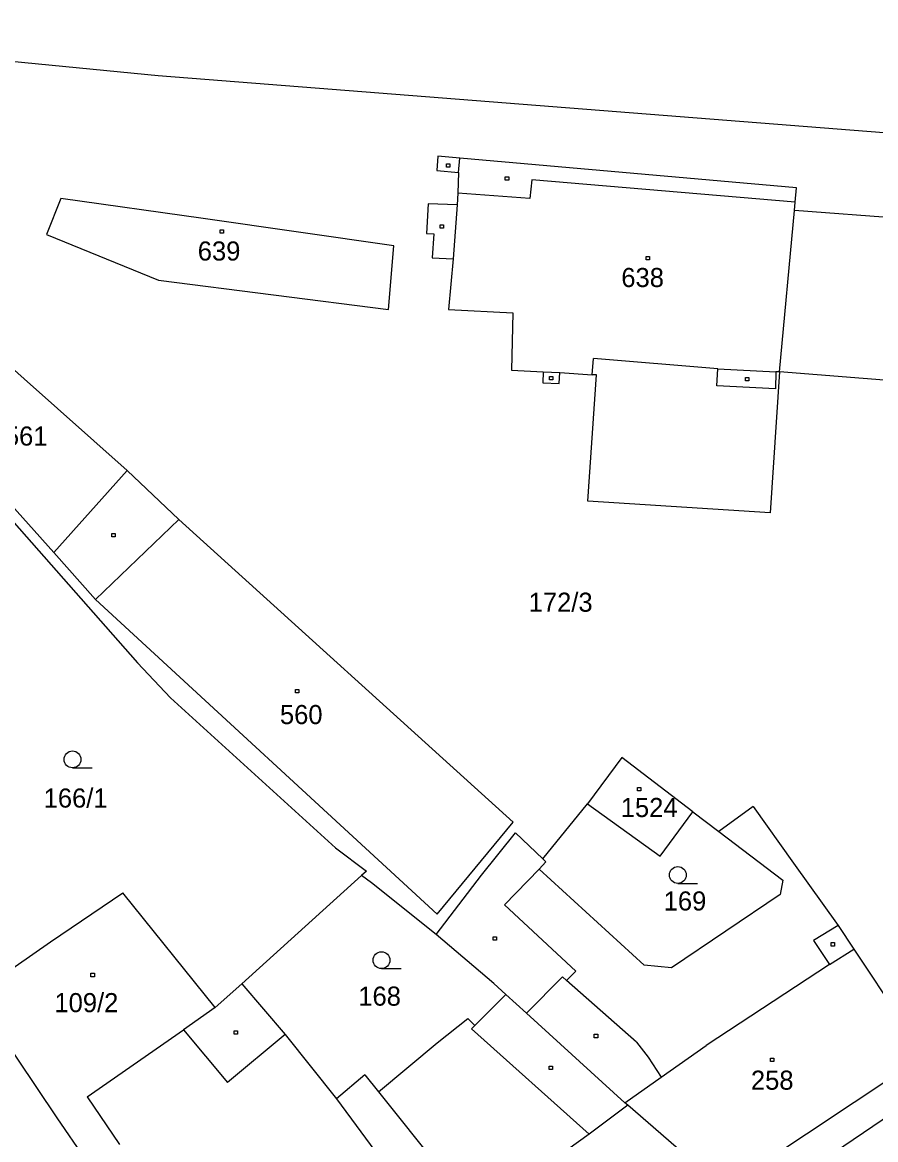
# Model space of a CAD drawing. Extents: x -711879 to -711361, y -1048782 to -1048177.
# Drawn here: x -711745.8 to -711669.9, y -1048542.7 to -1048443.3 of the extents above; entities that cross this region are included whole.
import ezdxf

# ---------------------------------------------------------------- set-up
doc = ezdxf.new("R2010")
doc.units = 0
for name, color, linetype in [('Vrstva 1', 7, 'Continuous'), ('Vrstva 14', 7, 'Continuous'), ('Vrstva 15', 7, 'Continuous'), ('Vrstva 2', 7, 'Continuous'), ('Vrstva 23', 7, 'Continuous'), ('Vrstva 25', 7, 'Continuous'), ('Vrstva 46', 7, 'Continuous')]:
    doc.layers.add(name, color=color, linetype=linetype)

msp = doc.modelspace()

# ---------------------------------------------------------------- linework, layer by layer
at = {"layer": 'Vrstva 1'}
for p, q in [((-711782.37, -1048443.28), (-711733.69, -1048448.01)), ((-711733.69, -1048448.01), (-711654.61, -1048454.24)), ((-711708.81, -1048455.2), (-711708.89, -1048456.47)), ((-711706.85, -1048455.37), (-711708.81, -1048455.2)), ((-711676.89, -1048458), (-711706.85, -1048455.37)), ((-711708.89, -1048456.47), (-711706.96, -1048456.63)), ((-711706.96, -1048456.63), (-711707.02, -1048458.48)), ((-711707.02, -1048458.48), (-711707.08, -1048459.53)), ((-711677.03, -1048459.27), (-711676.89, -1048458)), ((-711742.35, -1048458.96), (-711743.64, -1048462.17)), ((-711729.69, -1048460.74), (-711742.35, -1048458.96)), ((-711709.66, -1048459.43), (-711709.82, -1048462.08)), ((-711707.08, -1048459.53), (-711709.66, -1048459.43)), ((-711677.08, -1048460.02), (-711677.03, -1048459.27)), ((-711678.42, -1048474.4), (-711677.08, -1048460.02)), ((-711660, -1048461.34), (-711677.08, -1048460.02)), ((-711712.73, -1048463.18), (-711729.69, -1048460.74)), ((-711743.64, -1048462.17), (-711733.67, -1048466.24)), ((-711709.82, -1048462.08), (-711709.17, -1048462.11)), ((-711709.17, -1048462.11), (-711709.33, -1048464.24)), ((-711713.2, -1048468.83), (-711712.73, -1048463.18)), ((-711709.33, -1048464.24), (-711707.46, -1048464.32)), ((-711707.46, -1048464.32), (-711707.87, -1048468.83)), ((-711733.67, -1048466.24), (-711713.2, -1048468.83)), ((-711707.87, -1048468.83), (-711702.15, -1048469.14)), ((-711702.15, -1048469.14), (-711702.26, -1048474.24)), ((-711747.61, -1048473.24), (-711745.62, -1048475.02)), ((-711702.26, -1048474.24), (-711699.43, -1048474.38)), ((-711699.43, -1048474.38), (-711699.47, -1048475.36)), ((-711698.02, -1048475.42), (-711697.97, -1048474.45)), ((-711697.97, -1048474.45), (-711695.09, -1048474.64)), ((-711678.42, -1048474.4), (-711679.25, -1048486.93)), ((-711648.15, -1048476.76), (-711678.42, -1048474.4)), ((-711745.62, -1048475.02), (-711736.45, -1048483.16)), ((-711699.47, -1048475.36), (-711698.02, -1048475.42)), ((-711695.47, -1048485.89), (-711694.7, -1048474.65)), ((-711694.7, -1048474.65), (-711695.09, -1048474.64)), ((-711742.97, -1048490.46), (-711753.19, -1048479.09)), ((-711736.45, -1048483.16), (-711731.85, -1048487.53)), ((-711679.25, -1048486.93), (-711695.47, -1048485.89)), ((-711747.16, -1048487.08), (-711735.52, -1048500.3)), ((-711731.85, -1048487.53), (-711739.27, -1048494.66)), ((-711702.1, -1048514.46), (-711731.85, -1048487.53)), ((-711739.27, -1048494.66), (-711742.97, -1048490.46)), ((-711739.27, -1048494.66), (-711708.88, -1048522.66)), ((-711735.52, -1048500.3), (-711732.59, -1048503.39)), ((-711732.59, -1048503.39), (-711717.93, -1048516.75)), ((-711692.45, -1048508.71), (-711695.49, -1048512.83)), ((-711686.12, -1048513.55), (-711692.45, -1048508.71)), ((-711699.48, -1048517.72), (-711695.49, -1048512.83)), ((-711695.49, -1048512.83), (-711689.04, -1048517.5)), ((-711680.76, -1048513.07), (-711683.81, -1048515.31)), ((-711680.76, -1048513.07), (-711677.16, -1048518.12)), ((-711689.04, -1048517.5), (-711686.12, -1048513.55)), ((-711686.12, -1048513.55), (-711683.81, -1048515.31)), ((-711708.88, -1048522.66), (-711702.1, -1048514.46)), ((-711704.92, -1048519.17), (-711701.89, -1048515.43)), ((-711701.89, -1048515.43), (-711699.48, -1048517.72)), ((-711683.81, -1048515.31), (-711678.11, -1048519.64)), ((-711717.93, -1048516.75), (-711715.17, -1048518.83)), ((-711699.8, -1048518.66), (-711699.2, -1048518)), ((-711699.2, -1048518), (-711699.48, -1048517.72)), ((-711677.16, -1048518.12), (-711673.19, -1048523.66)), ((-711715.59, -1048519.2), (-711726.24, -1048528.87)), ((-711715.17, -1048518.83), (-711715.59, -1048519.2)), ((-711714.72, -1048519.88), (-711715.59, -1048519.2)), ((-711708.95, -1048524.46), (-711704.92, -1048519.17)), ((-711690.45, -1048527.19), (-711699.8, -1048518.66)), ((-711708.95, -1048524.46), (-711714.72, -1048519.88)), ((-711678.11, -1048519.64), (-711678.37, -1048520.9)), ((-711743.26, -1048525.11), (-711736.84, -1048520.76)), ((-711728.61, -1048530.95), (-711736.84, -1048520.76)), ((-711678.37, -1048520.9), (-711688.03, -1048527.44)), ((-711673.19, -1048523.66), (-711671.8, -1048525.77)), ((-711750.06, -1048529.83), (-711743.26, -1048525.11)), ((-711703.83, -1048528.84), (-711708.95, -1048524.46)), ((-711671.8, -1048525.77), (-711665.54, -1048535.25)), ((-711688.03, -1048527.44), (-711690.45, -1048527.19)), ((-711728.61, -1048530.95), (-711726.24, -1048528.87)), ((-711726.24, -1048528.87), (-711722.39, -1048533.38)), ((-711702.77, -1048529.8), (-711703.83, -1048528.84)), ((-711705.52, -1048532.56), (-711702.77, -1048529.8)), ((-711700.91, -1048531.48), (-711702.77, -1048529.8)), ((-711728.61, -1048530.95), (-711731.45, -1048532.94)), ((-711742.68, -1048540.77), (-711748.68, -1048531.86)), ((-711708.87, -1048534.1), (-711706.14, -1048531.93)), ((-711706.14, -1048531.93), (-711705.52, -1048532.56)), ((-711692.18, -1048539.46), (-711700.91, -1048531.48)), ((-711740.02, -1048538.92), (-711731.45, -1048532.94)), ((-711722.39, -1048533.38), (-711717.84, -1048539.08)), ((-711714.1, -1048538.46), (-711708.87, -1048534.1)), ((-711683.36, -1048547.06), (-711665.54, -1048535.25)), ((-711715.3, -1048536.96), (-711717.84, -1048539.08)), ((-711715.3, -1048536.96), (-711714.1, -1048538.46)), ((-711740.02, -1048538.92), (-711737.13, -1048543.16)), ((-711717.84, -1048539.08), (-711710.59, -1048548.86)), ((-711691.92, -1048539.67), (-711692.18, -1048539.46)), ((-711683.36, -1048547.06), (-711691.92, -1048539.67)), ((-711740.17, -1048544.47), (-711742.68, -1048540.77))]:
    msp.add_line(p, q, dxfattribs=at)
at = {"layer": 'Vrstva 2'}
for p, q in [((-711706.96, -1048456.63), (-711706.85, -1048455.37)), ((-711700.46, -1048457.3), (-711700.63, -1048458.96)), ((-711677.03, -1048459.27), (-711700.46, -1048457.3)), ((-711700.63, -1048458.96), (-711707.02, -1048458.48)), ((-711707.08, -1048459.53), (-711707.46, -1048464.32)), ((-711695.09, -1048474.64), (-711694.97, -1048473.2)), ((-711683.91, -1048474.12), (-711694.97, -1048473.2)), ((-711699.43, -1048474.38), (-711697.97, -1048474.45)), ((-711683.99, -1048475.62), (-711683.91, -1048474.12)), ((-711683.91, -1048474.12), (-711678.75, -1048474.4)), ((-711678.75, -1048474.4), (-711678.77, -1048475.89)), ((-711678.42, -1048474.4), (-711678.75, -1048474.4)), ((-711678.77, -1048475.89), (-711683.99, -1048475.62)), ((-711736.45, -1048483.16), (-711742.97, -1048490.46)), ((-711702.88, -1048521.82), (-711699.8, -1048518.66)), ((-711696.54, -1048527.72), (-711702.88, -1048521.82)), ((-711673.19, -1048523.66), (-711675.38, -1048525.01)), ((-711675.38, -1048525.01), (-711673.98, -1048527.15)), ((-711673.98, -1048527.15), (-711671.8, -1048525.77)), ((-711673.98, -1048527.15), (-711684.94, -1048534.35)), ((-711697.36, -1048528.55), (-711696.54, -1048527.72)), ((-711697.71, -1048528.24), (-711700.91, -1048531.48)), ((-711697.36, -1048528.55), (-711697.71, -1048528.24)), ((-711691.14, -1048534.05), (-711697.36, -1048528.55)), ((-711731.45, -1048532.94), (-711727.52, -1048537.64)), ((-711705.81, -1048532.86), (-711705.52, -1048532.56)), ((-711705.81, -1048532.86), (-711695.34, -1048542.23)), ((-711722.39, -1048533.38), (-711727.52, -1048537.64)), ((-711691.14, -1048534.05), (-711690.09, -1048535.37)), ((-711688.94, -1048537.17), (-711684.94, -1048534.35)), ((-711690.09, -1048535.37), (-711688.94, -1048537.17)), ((-711692.52, -1048556.74), (-711664.62, -1048537.77)), ((-711692.18, -1048539.46), (-711688.94, -1048537.17)), ((-711714.1, -1048538.46), (-711713.84, -1048538.78)), ((-711713.84, -1048538.78), (-711707.75, -1048546.38)), ((-711691.92, -1048539.67), (-711695.34, -1048542.23)), ((-711695.34, -1048542.23), (-711700.32, -1048545.78))]:
    msp.add_line(p, q, dxfattribs=at)
at = {"layer": 'Vrstva 23'}
for p, q in [((-711741.31, -1048509.63), (-711739.56, -1048509.63)), ((-711687.46, -1048519.92), (-711685.71, -1048519.92)), ((-711713.82, -1048527.5), (-711712.07, -1048527.5))]:
    msp.add_line(p, q, dxfattribs=at)
for centre in [(-711741.31, -1048508.88), (-711687.46, -1048519.17), (-711713.82, -1048526.75)]:
    msp.add_circle(centre, 0.75, dxfattribs=at)
at = {"layer": 'Vrstva 25'}
for p, q in [((-711708.05, -1048455.87), (-711707.75, -1048455.87)), ((-711708.05, -1048456.17), (-711708.05, -1048455.87)), ((-711707.75, -1048456.17), (-711708.05, -1048456.17)), ((-711707.75, -1048455.87), (-711707.75, -1048456.17)), ((-711702.81, -1048457.03), (-711702.51, -1048457.03)), ((-711702.81, -1048457.33), (-711702.81, -1048457.03)), ((-711702.51, -1048457.33), (-711702.81, -1048457.33)), ((-711702.51, -1048457.03), (-711702.51, -1048457.33)), ((-711708.6, -1048461.3), (-711708.3, -1048461.3)), ((-711708.6, -1048461.6), (-711708.6, -1048461.3)), ((-711708.3, -1048461.3), (-711708.3, -1048461.6)), ((-711728.17, -1048461.74), (-711727.87, -1048461.74)), ((-711728.17, -1048462.04), (-711728.17, -1048461.74)), ((-711727.87, -1048462.04), (-711728.17, -1048462.04)), ((-711727.87, -1048461.74), (-711727.87, -1048462.04)), ((-711708.3, -1048461.6), (-711708.6, -1048461.6)), ((-711690.29, -1048464.13), (-711689.99, -1048464.13)), ((-711690.29, -1048464.43), (-711690.29, -1048464.13)), ((-711689.99, -1048464.43), (-711690.29, -1048464.43)), ((-711689.99, -1048464.13), (-711689.99, -1048464.43)), ((-711698.88, -1048474.8), (-711698.58, -1048474.8)), ((-711698.88, -1048475.1), (-711698.88, -1048474.8)), ((-711698.58, -1048475.1), (-711698.88, -1048475.1)), ((-711698.58, -1048474.8), (-711698.58, -1048475.1)), ((-711681.43, -1048474.9), (-711681.13, -1048474.9)), ((-711681.43, -1048475.2), (-711681.43, -1048474.9)), ((-711681.13, -1048475.2), (-711681.43, -1048475.2)), ((-711681.13, -1048474.9), (-711681.13, -1048475.2)), ((-711737.82, -1048488.78), (-711737.52, -1048488.78)), ((-711737.82, -1048489.08), (-711737.82, -1048488.78)), ((-711737.52, -1048489.08), (-711737.82, -1048489.08)), ((-711737.52, -1048488.78), (-711737.52, -1048489.08)), ((-711721.47, -1048502.66), (-711721.17, -1048502.66)), ((-711721.47, -1048502.96), (-711721.47, -1048502.66)), ((-711721.17, -1048502.96), (-711721.47, -1048502.96)), ((-711721.17, -1048502.66), (-711721.17, -1048502.96)), ((-711691.05, -1048511.37), (-711690.75, -1048511.37)), ((-711691.05, -1048511.67), (-711691.05, -1048511.37)), ((-711690.75, -1048511.67), (-711691.05, -1048511.67)), ((-711690.75, -1048511.37), (-711690.75, -1048511.67)), ((-711703.9, -1048524.68), (-711703.6, -1048524.68)), ((-711703.9, -1048524.98), (-711703.9, -1048524.68)), ((-711703.6, -1048524.98), (-711703.9, -1048524.98)), ((-711703.6, -1048524.68), (-711703.6, -1048524.98)), ((-711673.82, -1048525.19), (-711673.52, -1048525.19)), ((-711673.82, -1048525.49), (-711673.82, -1048525.19)), ((-711673.52, -1048525.19), (-711673.52, -1048525.49)), ((-711673.52, -1048525.49), (-711673.82, -1048525.49)), ((-711739.67, -1048527.92), (-711739.37, -1048527.92)), ((-711739.67, -1048528.22), (-711739.67, -1048527.92)), ((-711739.37, -1048527.92), (-711739.37, -1048528.22)), ((-711739.37, -1048528.22), (-711739.67, -1048528.22)), ((-711726.94, -1048533.04), (-711726.64, -1048533.04)), ((-711726.94, -1048533.34), (-711726.94, -1048533.04)), ((-711726.64, -1048533.04), (-711726.64, -1048533.34)), ((-711726.64, -1048533.34), (-711726.94, -1048533.34)), ((-711694.89, -1048533.35), (-711694.59, -1048533.35)), ((-711694.89, -1048533.65), (-711694.89, -1048533.35)), ((-711694.59, -1048533.65), (-711694.89, -1048533.65)), ((-711694.59, -1048533.35), (-711694.59, -1048533.65)), ((-711679.22, -1048535.48), (-711678.92, -1048535.48)), ((-711679.22, -1048535.78), (-711679.22, -1048535.48)), ((-711678.92, -1048535.78), (-711679.22, -1048535.78)), ((-711678.92, -1048535.48), (-711678.92, -1048535.78)), ((-711698.91, -1048536.18), (-711698.61, -1048536.18)), ((-711698.91, -1048536.48), (-711698.91, -1048536.18)), ((-711698.61, -1048536.48), (-711698.91, -1048536.48)), ((-711698.61, -1048536.18), (-711698.61, -1048536.48))]:
    msp.add_line(p, q, dxfattribs=at)
at = {"layer": 'Vrstva 46'}
for p, q in [((-711694.97, -1048473.2), (-711694.97, -1048473.2)), ((-711683.91, -1048474.12), (-711683.91, -1048474.12)), ((-711678.75, -1048474.4), (-711678.75, -1048474.4)), ((-711678.42, -1048474.4), (-711678.42, -1048474.4)), ((-711695.09, -1048474.64), (-711695.09, -1048474.64)), ((-711678.77, -1048475.89), (-711678.77, -1048475.89)), ((-711735.52, -1048500.3), (-711735.52, -1048500.3)), ((-711732.59, -1048503.39), (-711732.59, -1048503.39)), ((-711717.93, -1048516.75), (-711717.93, -1048516.75)), ((-711704.92, -1048519.17), (-711704.92, -1048519.17)), ((-711673.19, -1048523.66), (-711673.19, -1048523.66)), ((-711743.26, -1048525.11), (-711743.26, -1048525.11)), ((-711675.38, -1048525.01), (-711675.38, -1048525.01)), ((-711673.98, -1048527.15), (-711673.98, -1048527.15)), ((-711728.61, -1048530.95), (-711728.61, -1048530.95)), ((-711731.45, -1048532.94), (-711731.45, -1048532.94)), ((-711691.14, -1048534.05), (-711691.14, -1048534.05)), ((-711684.94, -1048534.35), (-711684.94, -1048534.35)), ((-711690.09, -1048535.37), (-711690.09, -1048535.37)), ((-711727.52, -1048537.64), (-711727.52, -1048537.64)), ((-711740.02, -1048538.92), (-711740.02, -1048538.92))]:
    msp.add_line(p, q, dxfattribs=at)

# ---------------------------------------------------------------- texts
at = {"layer": 'Vrstva 14'}
for s, p in [('172/3', (-711700.73, -1048495.74)), ('166/1', (-711743.88, -1048513.17)), ('169', (-711688.72, -1048522.33)), ('168', (-711715.89, -1048530.8))]:
    msp.add_text(s, height=1.7, dxfattribs=at).set_placement(p)
at = {"layer": 'Vrstva 15'}
for s, p in [('639', (-711730.17, -1048464.48)), ('638', (-711692.49, -1048466.84)), ('561', (-711747.33, -1048480.95)), ('560', (-711722.86, -1048505.74)), ('1524', (-711692.54, -1048514.01)), ('109/2', (-711742.922, -1048531.38)), ('258', (-711680.96, -1048538.28))]:
    msp.add_text(s, height=1.7, dxfattribs=at).set_placement(p)

doc.saveas('drawing.dxf')
